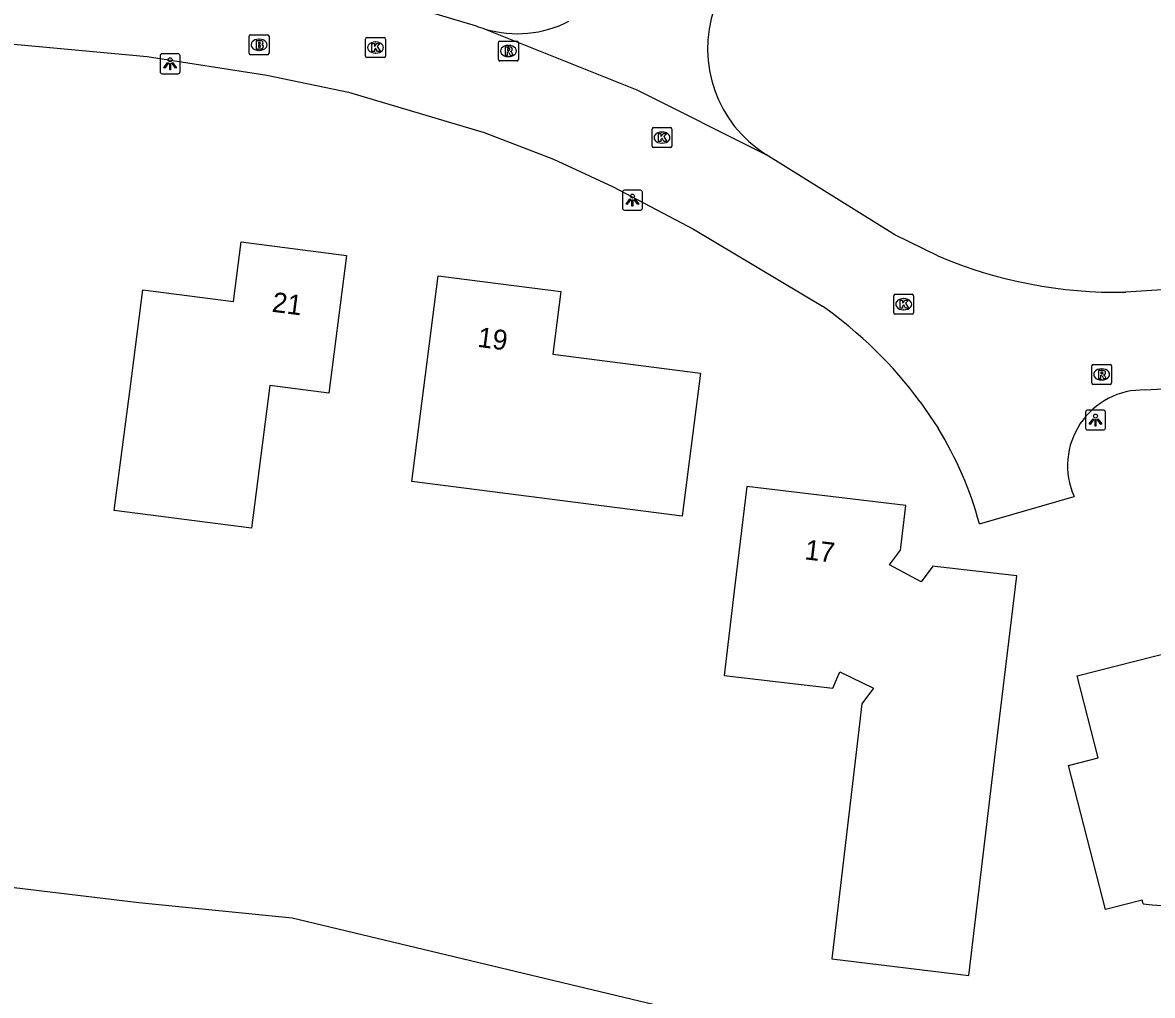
# Model space of a CAD drawing. Extents: x 163268 to 164360, y 381529 to 382285.
# Drawn here: x 163454.1 to 163510.8, y 381611.3 to 381660.1 of the extents above; entities that cross this region are included whole.
import ezdxf

# ---------------------------------------------------------------- set-up
doc = ezdxf.new("R2010")
doc.units = 0
for name, color, linetype in [('IMGEO_Brandkraan', 7, 'Continuous'), ('IMGEO_Kolk', 7, 'Continuous'), ('IMGEO_Lichtpunt', 7, 'Continuous'), ('IMGEO_Loofbos', 7, 'Continuous'), ('IMGEO_Pand', 7, 'Continuous'), ('IMGEO_Pand_nummerreeks', 7, 'Continuous'), ('IMGEO_Rijbaan_lokaal_open', 7, 'Continuous'), ('IMGEO_Rioolput', 7, 'Continuous')]:
    doc.layers.add(name, color=color, linetype=linetype)

msp = doc.modelspace()

# ---------------------------------------------------------------- linework, layer by layer
at = {"layer": 'IMGEO_Brandkraan'}
for p, q in [((163465.445, 381658.536), (163465.445, 381659.388)), ((163465.52, 381659.462), (163466.372, 381659.462)), ((163466.446, 381659.388), (163466.446, 381658.536)), ((163465.933, 381659.242), (163465.958, 381659.242)), ((163466.372, 381658.462), (163465.52, 381658.462)), ((163465.956, 381658.682), (163465.931, 381658.682))]:
    msp.add_line(p, q, dxfattribs=at)
for points in [[(163465.445, 381658.536), (163465.445, 381659.388)], [(163465.52, 381659.462), (163466.372, 381659.462)], [(163466.446, 381659.388), (163466.446, 381658.536)], [(163465.793, 381659.162), (163465.793, 381658.762), (163466.006, 381658.762)], [(163466.024, 381659.162), (163465.793, 381659.162)], [(163465.972, 381659.081), (163465.918, 381659.081), (163465.918, 381659.005)], [(163465.918, 381659.005), (163465.971, 381659.005)], [(163465.98, 381658.929), (163465.918, 381658.929), (163465.918, 381658.848)], [(163465.918, 381658.848), (163465.98, 381658.848)], [(163466.372, 381658.462), (163465.52, 381658.462)]]:
    msp.add_lwpolyline(points, dxfattribs=at)
for centre, radius, start, end in [((163465.522, 381659.386), 0.0765, 91.552, 178.448), ((163465.522, 381659.386), 0.0765, 91.552, 178.448), ((163466.37, 381659.386), 0.0765, 1.552, 88.448), ((163466.37, 381659.386), 0.0765, 1.552, 88.448), ((163465.973, 381659.043), 0.0379, 267.8285, 90.9355), ((163465.981, 381658.888), 0.0404, 269.8759, 90.5077), ((163466.012, 381659.013), 0.251, 268.6676, 293.5347), ((163466.028, 381659.017), 0.145, 59.4692, 91.5367), ((163466.053, 381659.064), 0.0922, 285.5137, 58.1501), ((163466.058, 381658.872), 0.105, 301.3115, 78.989), ((163465.522, 381658.538), 0.0765, 181.552, 268.448), ((163465.522, 381658.538), 0.0765, 181.552, 268.448), ((163466.37, 381658.538), 0.0765, 271.552, 358.448), ((163466.37, 381658.538), 0.0765, 271.552, 358.448)]:
    msp.add_arc(centre, radius, start, end, dxfattribs=at)
for centre, major_axis, ratio, start_param, end_param in [((163465.932, 381658.962), (-0.387, 0.002), 0.722429, 4.712389, 7.853982), ((163465.957, 381658.962), (-0.39, 0.002), 0.717154, 1.570796, 4.712389)]:
    msp.add_ellipse(centre, major_axis=major_axis, ratio=ratio, start_param=start_param, end_param=end_param, dxfattribs=at)
at = {"layer": 'IMGEO_Kolk'}
for p, q in [((163471.361, 381659.325), (163472.213, 381659.325)), ((163471.286, 381658.399), (163471.286, 381659.251)), ((163471.774, 381659.105), (163471.799, 381659.105)), ((163472.287, 381659.251), (163472.287, 381658.399)), ((163472.213, 381658.325), (163471.361, 381658.325)), ((163471.797, 381658.545), (163471.772, 381658.545)), ((163485.732, 381654.805), (163486.584, 381654.805)), ((163485.657, 381653.879), (163485.657, 381654.731)), ((163486.145, 381654.585), (163486.17, 381654.585)), ((163486.658, 381654.731), (163486.658, 381653.879)), ((163486.584, 381653.805), (163485.732, 381653.805)), ((163486.168, 381654.025), (163486.143, 381654.025)), ((163497.781, 381645.518), (163497.781, 381646.37)), ((163497.856, 381646.444), (163498.708, 381646.444)), ((163498.782, 381646.37), (163498.782, 381645.518)), ((163498.269, 381646.224), (163498.294, 381646.224)), ((163498.708, 381645.444), (163497.856, 381645.444)), ((163498.292, 381645.664), (163498.267, 381645.664))]:
    msp.add_line(p, q, dxfattribs=at)
for points in [[(163471.361, 381659.325), (163472.213, 381659.325)], [(163471.286, 381658.399), (163471.286, 381659.251)], [(163471.607, 381659.025), (163471.73, 381659.025), (163471.73, 381658.874), (163471.86, 381659.025), (163472.024, 381659.025), (163471.878, 381658.874), (163472.031, 381658.625), (163471.879, 381658.625), (163471.794, 381658.789), (163471.73, 381658.722), (163471.73, 381658.625), (163471.607, 381658.625), (163471.607, 381659.025)], [(163472.287, 381659.251), (163472.287, 381658.399)], [(163472.213, 381658.325), (163471.361, 381658.325)], [(163485.732, 381654.805), (163486.584, 381654.805)], [(163485.657, 381653.879), (163485.657, 381654.731)], [(163485.978, 381654.505), (163486.101, 381654.505), (163486.101, 381654.354), (163486.231, 381654.505), (163486.395, 381654.505), (163486.249, 381654.354), (163486.402, 381654.105), (163486.25, 381654.105), (163486.165, 381654.269), (163486.101, 381654.202), (163486.101, 381654.105), (163485.978, 381654.105), (163485.978, 381654.505)], [(163486.658, 381654.731), (163486.658, 381653.879)], [(163486.584, 381653.805), (163485.732, 381653.805)], [(163497.781, 381645.518), (163497.781, 381646.37)], [(163497.856, 381646.444), (163498.708, 381646.444)], [(163498.782, 381646.37), (163498.782, 381645.518)], [(163498.102, 381646.144), (163498.225, 381646.144), (163498.225, 381645.993), (163498.355, 381646.144), (163498.519, 381646.144), (163498.373, 381645.993), (163498.526, 381645.744), (163498.374, 381645.744), (163498.289, 381645.908), (163498.225, 381645.841), (163498.225, 381645.744), (163498.102, 381645.744), (163498.102, 381646.144)], [(163498.708, 381645.444), (163497.856, 381645.444)]]:
    msp.add_lwpolyline(points, dxfattribs=at)
for centre, start, end in [((163471.363, 381659.249), 91.552, 178.448), ((163471.363, 381659.249), 91.552, 178.448), ((163472.211, 381659.249), 1.552, 88.448), ((163472.211, 381659.249), 1.552, 88.448), ((163471.363, 381658.401), 181.552, 268.448), ((163471.363, 381658.401), 181.552, 268.448), ((163472.211, 381658.401), 271.552, 358.448), ((163472.211, 381658.401), 271.552, 358.448), ((163485.734, 381654.729), 91.552, 178.448), ((163485.734, 381654.729), 91.552, 178.448), ((163486.582, 381654.729), 1.552, 88.448), ((163486.582, 381654.729), 1.552, 88.448), ((163485.734, 381653.881), 181.552, 268.448), ((163485.734, 381653.881), 181.552, 268.448), ((163486.582, 381653.881), 271.552, 358.448), ((163486.582, 381653.881), 271.552, 358.448), ((163497.858, 381646.368), 91.552, 178.448), ((163497.858, 381646.368), 91.552, 178.448), ((163498.706, 381646.368), 1.552, 88.448), ((163498.706, 381646.368), 1.552, 88.448), ((163497.858, 381645.52), 181.552, 268.448), ((163497.858, 381645.52), 181.552, 268.448), ((163498.706, 381645.52), 271.552, 358.448), ((163498.706, 381645.52), 271.552, 358.448)]:
    msp.add_arc(centre, 0.0765, start, end, dxfattribs=at)
for centre, major_axis, ratio, start_param, end_param in [((163471.773, 381658.825), (-0.387, 0.002), 0.722429, 4.712389, 7.853982), ((163471.798, 381658.825), (-0.39, 0.002), 0.717154, 1.570796, 4.712389), ((163486.144, 381654.305), (-0.387, 0.002), 0.722429, 4.712389, 7.853982), ((163486.169, 381654.305), (-0.39, 0.002), 0.717154, 1.570796, 4.712389), ((163498.268, 381645.944), (-0.387, 0.002), 0.722429, 4.712389, 7.853982), ((163498.293, 381645.944), (-0.39, 0.002), 0.717154, 1.570796, 4.712389)]:
    msp.add_ellipse(centre, major_axis=major_axis, ratio=ratio, start_param=start_param, end_param=end_param, dxfattribs=at)
at = {"layer": 'IMGEO_Lichtpunt'}
for p, q in [((163460.986, 381658.413), (163460.986, 381657.606)), ((163460.986, 381658.413), (163460.986, 381657.606)), ((163461.888, 381658.508), (163461.08, 381658.508)), ((163461.888, 381658.508), (163461.08, 381658.508)), ((163461.982, 381657.606), (163461.982, 381658.413)), ((163461.982, 381657.606), (163461.982, 381658.413)), ((163461.08, 381657.512), (163461.888, 381657.512)), ((163461.08, 381657.512), (163461.888, 381657.512)), ((163484.177, 381651.57), (163484.177, 381650.763)), ((163484.177, 381651.57), (163484.177, 381650.763)), ((163485.079, 381651.665), (163484.271, 381651.665)), ((163485.079, 381651.665), (163484.271, 381651.665)), ((163485.173, 381650.763), (163485.173, 381651.57)), ((163485.173, 381650.763), (163485.173, 381651.57)), ((163484.271, 381650.669), (163485.079, 381650.669)), ((163484.271, 381650.669), (163485.079, 381650.669)), ((163508.307, 381640.631), (163507.499, 381640.631)), ((163508.307, 381640.631), (163507.499, 381640.631)), ((163507.405, 381640.536), (163507.405, 381639.729)), ((163507.405, 381640.536), (163507.405, 381639.729)), ((163508.401, 381639.729), (163508.401, 381640.536)), ((163508.401, 381639.729), (163508.401, 381640.536)), ((163507.499, 381639.635), (163508.307, 381639.635)), ((163507.499, 381639.635), (163508.307, 381639.635))]:
    msp.add_line(p, q, dxfattribs=at)
for points in [[(163461.36, 381658.077), (163461.399, 381658.049), (163461.211, 381657.787), (163461.173, 381657.814), (163461.36, 381658.077)], [(163461.462, 381658.029), (163461.509, 381658.029), (163461.509, 381657.707), (163461.462, 381657.707), (163461.462, 381658.029)], [(163461.572, 381658.049), (163461.61, 381658.076), (163461.797, 381657.814), (163461.758, 381657.786), (163461.572, 381658.049)], [(163484.551, 381651.234), (163484.59, 381651.206), (163484.402, 381650.944), (163484.364, 381650.971), (163484.551, 381651.234)], [(163484.653, 381651.186), (163484.7, 381651.186), (163484.7, 381650.864), (163484.653, 381650.864), (163484.653, 381651.186)], [(163484.763, 381651.206), (163484.801, 381651.233), (163484.988, 381650.971), (163484.949, 381650.943), (163484.763, 381651.206)], [(163507.779, 381640.2), (163507.818, 381640.172), (163507.63, 381639.91), (163507.592, 381639.937), (163507.779, 381640.2)], [(163507.881, 381640.152), (163507.928, 381640.152), (163507.928, 381639.83), (163507.881, 381639.83), (163507.881, 381640.152)], [(163507.991, 381640.172), (163508.029, 381640.199), (163508.216, 381639.937), (163508.177, 381639.909), (163507.991, 381640.172)]]:
    msp.add_lwpolyline(points, dxfattribs=at)
for centre in [(163461.485, 381658.211), (163484.676, 381651.368), (163507.904, 381640.334)]:
    msp.add_circle(centre, 0.0994, dxfattribs=at)
for centre, start, end in [((163461.08, 381658.413), 90, 180), ((163461.08, 381658.413), 90, 180), ((163461.888, 381658.413), 0, 90), ((163461.888, 381658.413), 0, 90), ((163461.08, 381657.606), 180, 270), ((163461.08, 381657.606), 180, 270), ((163461.888, 381657.606), 270, 0), ((163461.888, 381657.606), 270, 360), ((163484.271, 381651.57), 90, 180), ((163484.271, 381651.57), 90, 180), ((163485.079, 381651.57), 0, 90), ((163485.079, 381651.57), 0, 90), ((163484.271, 381650.763), 180, 270), ((163484.271, 381650.763), 180, 270), ((163485.079, 381650.763), 270, 0), ((163485.079, 381650.763), 270, 360), ((163507.499, 381640.536), 90, 180), ((163507.499, 381640.536), 90, 180), ((163508.307, 381640.536), 0, 90), ((163508.307, 381640.536), 0, 90), ((163507.499, 381639.729), 180, 270), ((163507.499, 381639.729), 180, 270), ((163508.307, 381639.729), 270, 0), ((163508.307, 381639.729), 270, 360)]:
    msp.add_arc(centre, 0.0946, start, end, dxfattribs=at)
at = {"layer": 'IMGEO_Loofbos'}
msp.add_lwpolyline([(163442.602, 381660.009), (163441.974, 381658.511), (163446.05, 381651.319), (163447.993, 381636.708), (163448.357, 381617.306), (163459.913, 381615.932), (163467.608, 381615.147), (163500.109, 381607.374), (163500.96, 381607.171), (163500.848, 381606.174), (163534.27, 381588.252), (163555.584, 381575.614)], dxfattribs=at)
at = {"layer": 'IMGEO_Pand'}
for points in [[(163469.443, 381641.485), (163466.489, 381641.865), (163465.568, 381634.704), (163458.685, 381635.589), (163459.472, 381641.705), (163460.108, 381646.663), (163464.658, 381646.079), (163465.043, 381649.074), (163470.331, 381648.394), (163469.695, 381643.436), (163469.443, 381641.485)], [(163480.688, 381643.441), (163488.089, 381642.489), (163487.453, 381637.531), (163487.166, 381635.306), (163473.612, 381637.048), (163474.301, 381642.408), (163474.938, 381647.367), (163481.091, 381646.576), (163480.688, 381643.441)], [(163503.954, 381632.309), (163500, 381632.766), (163499.738, 381632.796), (163499.16, 381632.021), (163497.578, 381632.872), (163498.122, 381633.6), (163498.388, 381635.846), (163490.408, 381636.792), (163489.819, 381631.827), (163489.284, 381627.317), (163494.724, 381626.672), (163495.081, 381627.501), (163496.772, 381626.673), (163496.187, 381625.89), (163495.95, 381623.887), (163494.672, 381613.09), (163501.548, 381612.265), (163502.845, 381623.069), (163503.358, 381627.345), (163503.954, 381632.309)], [(163510.291, 381615.854), (163510.242, 381616.047), (163508.401, 381615.576), (163506.551, 381622.803), (163508.033, 381623.183), (163506.981, 381627.29), (163514.673, 381629.26)]]:
    msp.add_lwpolyline(points, dxfattribs=at)
msp.add_arc((163511.569, 381625.383), 9.614, 262.3619, 306.355, dxfattribs=at)
at = {"layer": 'IMGEO_Rijbaan_lokaal_open'}
for points in [[(163437.182, 381666.013), (163442.176, 381665.079), (163448.608, 381664.27), (163455.329, 381663.829), (163457.86, 381663.79), (163462.224, 381663.302), (163472.048, 381661.348), (163476.829, 381659.912)], [(163442.602, 381660.009), (163460.334, 381658.369), (163466.34, 381657.437), (163470.435, 381656.592), (163477.242, 381654.553), (163480.719, 381653.221), (163483.709, 381651.834), (163487.738, 381649.717), (163494.209, 381645.839)], [(163477.288, 381659.754), (163484.894, 381656.697), (163491.371, 381653.46)], [(163500, 381648.371), (163497.846, 381649.421), (163491.371, 381653.46)], [(163510.388, 381641.642), (163518.174, 381642.091), (163517.692, 381647.078), (163509.418, 381646.546)], [(163499.105, 381641.046), (163500.007, 381639.728)], [(163502.08, 381634.928), (163506.83, 381636.302)]]:
    msp.add_lwpolyline(points, dxfattribs=at)
for centre, radius, start, end in [((163494.731, 381658.773), 6.287, 161.4036, 237.6877), ((163478.896, 381665.17), 5.65, 248.543, 253.4674), ((163478.903, 381665.211), 5.691, 253.5129, 297.0603), ((163508.97, 381669.447), 22.906, 246.9457, 271.1208), ((163482.189, 381628.663), 20.964, 36.2041, 55.0141), ((163510.297, 381637.847), 3.796, 88.6226, 204.027), ((163484.614, 381630.232), 18.086, 15.0474, 31.6692)]:
    msp.add_arc(centre, radius, start, end, dxfattribs=at)
at = {"layer": 'IMGEO_Rioolput'}
for p, q in [((163477.954, 381658.223), (163477.954, 381659.075)), ((163478.029, 381659.149), (163478.881, 381659.149)), ((163478.442, 381658.929), (163478.467, 381658.929)), ((163478.955, 381659.075), (163478.955, 381658.223)), ((163478.881, 381658.149), (163478.029, 381658.149)), ((163478.465, 381658.369), (163478.44, 381658.369)), ((163507.712, 381641.996), (163507.712, 381642.848)), ((163507.787, 381642.922), (163508.639, 381642.922)), ((163508.713, 381642.848), (163508.713, 381641.996)), ((163508.2, 381642.702), (163508.225, 381642.702)), ((163508.639, 381641.922), (163507.787, 381641.922)), ((163508.223, 381642.142), (163508.198, 381642.142))]:
    msp.add_line(p, q, dxfattribs=at)
for points in [[(163477.954, 381658.223), (163477.954, 381659.075)], [(163478.029, 381659.149), (163478.881, 381659.149)], [(163478.543, 381658.847), (163478.291, 381658.849), (163478.291, 381658.449)], [(163478.469, 381658.768), (163478.415, 381658.768), (163478.415, 381658.687)], [(163478.955, 381659.075), (163478.955, 381658.223)], [(163478.881, 381658.149), (163478.029, 381658.149)], [(163478.291, 381658.449), (163478.415, 381658.449), (163478.415, 381658.611), (163478.426, 381658.611)], [(163478.415, 381658.687), (163478.467, 381658.687)], [(163478.473, 381658.582), (163478.544, 381658.449), (163478.684, 381658.449), (163478.619, 381658.575)], [(163507.712, 381641.996), (163507.712, 381642.848)], [(163507.787, 381642.922), (163508.639, 381642.922)], [(163508.713, 381642.848), (163508.713, 381641.996)], [(163508.301, 381642.62), (163508.049, 381642.622), (163508.049, 381642.222)], [(163508.049, 381642.222), (163508.173, 381642.222), (163508.173, 381642.384), (163508.184, 381642.384)], [(163508.227, 381642.541), (163508.173, 381642.541), (163508.173, 381642.46)], [(163508.173, 381642.46), (163508.225, 381642.46)], [(163508.231, 381642.355), (163508.302, 381642.222), (163508.442, 381642.222), (163508.377, 381642.348)], [(163508.639, 381641.922), (163507.787, 381641.922)]]:
    msp.add_lwpolyline(points, dxfattribs=at)
for centre, radius, start, end in [((163478.031, 381659.073), 0.0765, 91.552, 178.448), ((163478.031, 381659.073), 0.0765, 91.552, 178.448), ((163478.475, 381658.672), 0.0964, 77.0061, 93.1865), ((163478.489, 381658.729), 0.0378, 276.6634, 79.6772), ((163478.542, 381658.737), 0.109, 350.3612, 89.416), ((163478.54, 381658.737), 0.112, 277.5842, 350.9817), ((163478.879, 381659.073), 0.0765, 1.552, 88.448), ((163478.879, 381659.073), 0.0765, 1.552, 88.448), ((163478.031, 381658.225), 0.0765, 181.552, 268.448), ((163478.031, 381658.225), 0.0765, 181.552, 268.448), ((163478.425, 381658.558), 0.0533, 26.0293, 88.6989), ((163478.451, 381658.876), 0.19, 274.7715, 282.9687), ((163478.524, 381658.522), 0.108, 29.5134, 73.7905), ((163478.879, 381658.225), 0.0765, 271.552, 358.448), ((163478.879, 381658.225), 0.0765, 271.552, 358.448), ((163507.789, 381642.846), 0.0765, 91.552, 178.448), ((163507.789, 381642.846), 0.0765, 91.552, 178.448), ((163508.637, 381642.846), 0.0765, 1.552, 88.448), ((163508.637, 381642.846), 0.0765, 1.552, 88.448), ((163508.183, 381642.331), 0.0533, 26.0293, 88.6989), ((163508.209, 381642.649), 0.19, 274.7715, 282.9687), ((163508.233, 381642.445), 0.0964, 77.0061, 93.1865), ((163508.247, 381642.502), 0.0378, 276.6634, 79.6772), ((163508.3, 381642.51), 0.109, 350.3612, 89.416), ((163508.298, 381642.51), 0.112, 277.5842, 350.9817), ((163508.282, 381642.295), 0.108, 29.5134, 73.7905), ((163507.789, 381641.998), 0.0765, 181.552, 268.448), ((163507.789, 381641.998), 0.0765, 181.552, 268.448), ((163508.637, 381641.998), 0.0765, 271.552, 358.448), ((163508.637, 381641.998), 0.0765, 271.552, 358.448)]:
    msp.add_arc(centre, radius, start, end, dxfattribs=at)
for centre, major_axis, ratio, start_param, end_param in [((163478.441, 381658.649), (-0.387, 0.002), 0.722429, 4.712389, 7.853982), ((163478.466, 381658.649), (-0.39, 0.002), 0.717154, 1.570796, 4.712389), ((163508.199, 381642.422), (-0.387, 0.002), 0.722429, 4.712389, 7.853982), ((163508.224, 381642.422), (-0.39, 0.002), 0.717154, 1.570796, 4.712389)]:
    msp.add_ellipse(centre, major_axis=major_axis, ratio=ratio, start_param=start_param, end_param=end_param, dxfattribs=at)

# ---------------------------------------------------------------- texts
at = {"layer": 'IMGEO_Pand_nummerreeks'}
for s, rotation, p in [('21', 352.6724, (163466.561, 381645.572)), ('19', 352.6745, (163476.867, 381643.812)), ('17', 353.2391, (163493.283, 381633.148))]:
    msp.add_text(s, height=1, rotation=rotation, dxfattribs=at).set_placement(p)

doc.saveas('drawing.dxf')
